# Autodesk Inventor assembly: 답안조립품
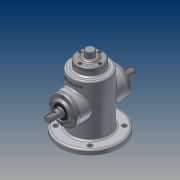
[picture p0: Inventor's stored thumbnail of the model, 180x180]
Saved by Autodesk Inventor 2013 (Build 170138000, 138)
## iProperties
Created: 2014-12
Part Number: 답안조립품
Document SubType Name: Assembly
Designer: CAD-B18
Author: CAD-B18
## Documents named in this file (12)
- C:\Users\CAD-B18\Desktop\441228V1010\답안조립품.iam
- C:\Users\CAD-B18\Desktop\441228V1010\본체.ipt
- C:\Users\CAD-B18\Desktop\441228V1010\베어링 6002.ipt
- 베어링 6002.ipt
- C:\Users\CAD-B18\Desktop\441228V1010\커버.ipt
- C:\Users\CAD-B18\Desktop\441228V1010\오일실.ipt
- 오일실.ipt
- C:\Users\CAD-B18\Desktop\441228V1010\축.ipt
- C:\Users\CAD-B18\Desktop\441228V1010\상단커버.ipt
- C:\Users\CAD-B18\Desktop\441228V1010\슬라이드.ipt
- C:\Users\CAD-B18\Desktop\441228V1010\M3x0.5x8.ipt
- M3x0.5.ipt
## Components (12 placed, 1 different names)
1. M3x0.5:9
2. M3x0.5:10
3. M3x0.5:11
4. M3x0.5:12
5. M3x0.5:2 — 각도:2
6. M3x0.5:3
7. M3x0.5:4
8. M3x0.5:5
9. M3x0.5:1 — 각도:3
10. M3x0.5:6
11. M3x0.5:7
12. M3x0.5:8
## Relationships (2: Angle 2)
- 각도:2 [Angle]: M3x0.5:2
- 각도:3 [Angle]: M3x0.5:1
